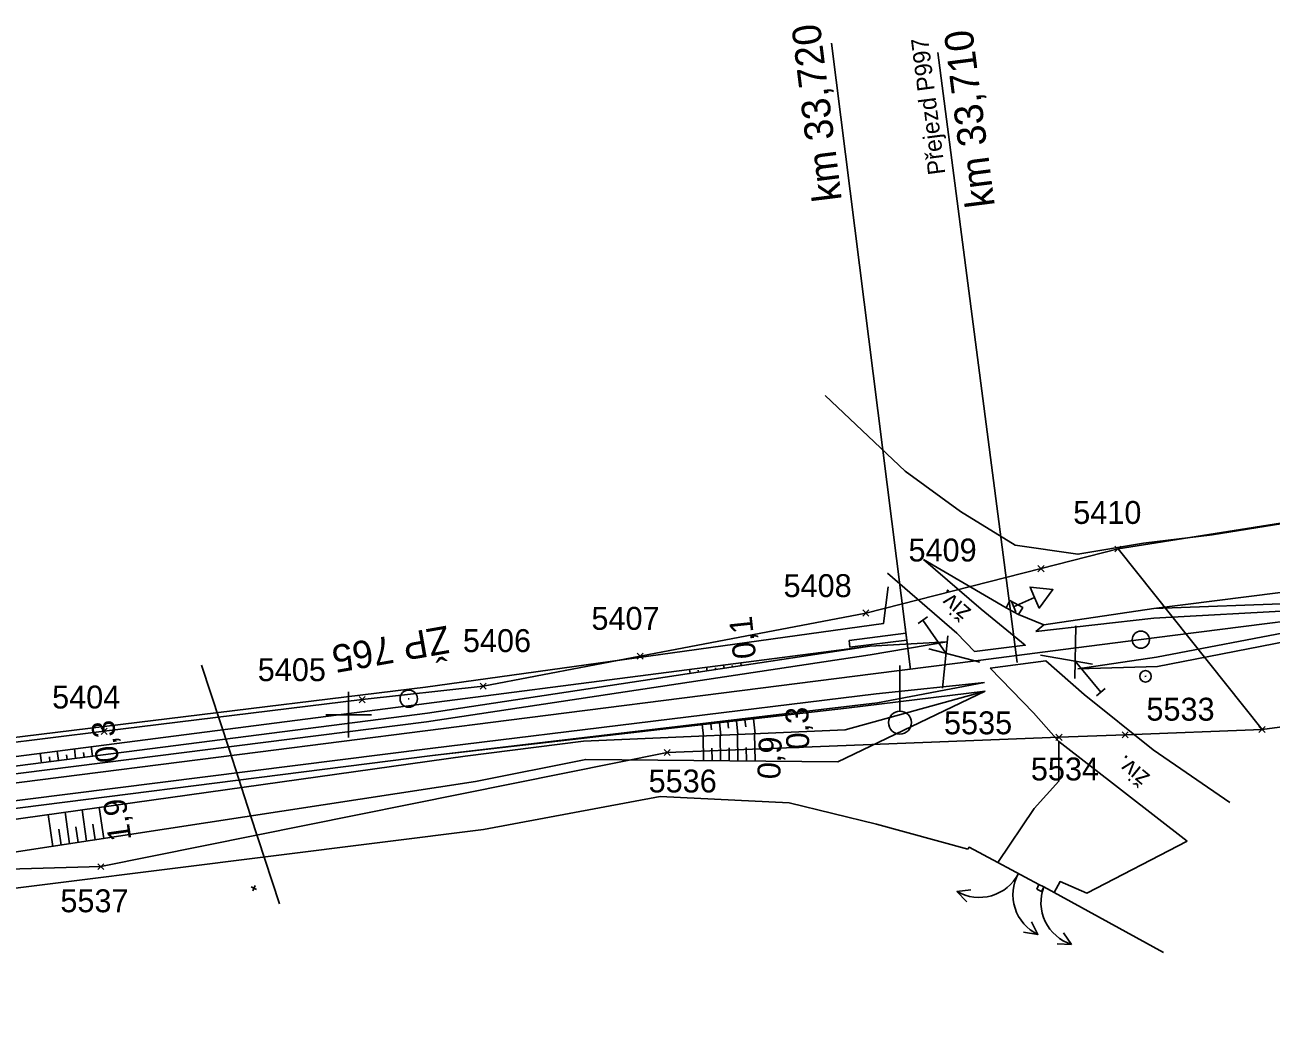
# Model space of a CAD drawing. Extents: x -805011 to -803920, y -1150790 to -1150234.
# Drawn here: x -804628.3 to -804519.5, y -1150528 to -1150439.8 of the extents above; entities that cross this region are included whole.
import ezdxf

# ---------------------------------------------------------------- set-up
doc = ezdxf.new("R2010")
doc.units = 0
for name, color, linetype in [('0381KM032-037P - Vrstva 1', 7, 'Continuous'), ('0381KM032-037P - Vrstva 12', 7, 'Continuous'), ('0381KM032-037P - Vrstva 17', 7, 'Continuous'), ('0381KM032-037P - Vrstva 25', 7, 'Continuous'), ('0381KM032-037P - Vrstva 36', 7, 'Continuous'), ('0381KM032-037P - Vrstva 4', 7, 'Continuous'), ('0381KM032-037P - Vrstva 48', 7, 'Continuous'), ('0381KM032-037P - Vrstva 49', 7, 'Continuous'), ('0381KM032-037P - Vrstva 51', 7, 'Continuous'), ('0381KM032-037P - Vrstva 55', 7, 'Continuous'), ('0381KM032-037P - Vrstva 7', 7, 'Continuous'), ('0381KM032-037P - Vrstva 9', 7, 'Continuous'), ('krizky_1000 - Vrstva 1', 7, 'Continuous'), ('szdc - hran DP', 7, 'Continuous'), ('szdc - szdc_cislo', 7, 'Continuous'), ('szdc - szdc_krizek', 7, 'Continuous'), ('vyt_sit - stávající', 7, 'Continuous')]:
    doc.layers.add(name, color=color, linetype=linetype)

msp = doc.modelspace()

# ---------------------------------------------------------------- linework, layer by layer
at = {"layer": '0381KM032-037P - Vrstva 1'}
msp.add_lwpolyline([(-804485.9, -1150487.74), (-804508.11, -1150490.55), (-804529.67, -1150493.3), (-804537.63, -1150494.31), (-804546.61, -1150495.46), (-804554.2, -1150496.42), (-804564.05, -1150497.67), (-804586.01, -1150500.48), (-804607.92, -1150503.26), (-804630.35, -1150506.11), (-804652.65, -1150508.9), (-804675.7, -1150511.78), (-804698.85, -1150514.71), (-804701.61, -1150515.06), (-804722.18, -1150517.67), (-804729.05, -1150518.54), (-804735.1, -1150519.31), (-804744.56, -1150520.5), (-804767.65, -1150523.46), (-804791, -1150526.42)], dxfattribs=at)
at = {"layer": '0381KM032-037P - Vrstva 12'}
for p, q in [((-804542.27, -1150490.03), (-804542.27, -1150490.03)), ((-804541.15, -1150490.64), (-804541.15, -1150490.64))]:
    msp.add_line(p, q, dxfattribs=at)
msp.add_lwpolyline([(-804542.6, -1150490.68), (-804542.27, -1150490.03), (-804541.15, -1150490.64), (-804541.52, -1150491.26), (-804542.6, -1150490.68), (-804542.27, -1150490.03), (-804541.15, -1150490.64), (-804541.52, -1150491.26)], dxfattribs=at)
at = {"layer": '0381KM032-037P - Vrstva 17'}
for p, q in [((-804553.92, -1150509.55), (-804545.93, -1150511.73)), ((-804539.31, -1150515.02), (-804528.85, -1150520.76)), ((-804546.89, -1150515.44), (-804546.02, -1150516.35)), ((-804539.82, -1150519.19), (-804541.07, -1150518.98)), ((-804536.89, -1150520.06), (-804537.59, -1150519.06)), ((-804538.15, -1150520.02), (-804536.89, -1150520.06)), ((-804536.89, -1150520.06), (-804538.15, -1150520.02))]:
    msp.add_line(p, q, dxfattribs=at)
for points in [[(-804368.54, -1150462.33), (-804374.42, -1150462.03), (-804388.45, -1150464.13), (-804427.08, -1150469.25), (-804429.72, -1150469.73), (-804431.75, -1150470.1), (-804437.24, -1150471.08), (-804446.96, -1150472.02), (-804473.97, -1150476), (-804503.76, -1150480.94), (-804524.61, -1150484.28), (-804530.6, -1150485.02), (-804536.33, -1150485.99), (-804541.81, -1150485.21), (-804546.58, -1150482.25), (-804551.41, -1150478.74), (-804558.4, -1150472.14)], [(-804552.89, -1150488.84), (-804553.29, -1150492.03), (-804593.3, -1150497.6), (-804640.86, -1150503.43), (-804657.42, -1150505.51), (-804657.62, -1150505.23), (-804688.14, -1150507.97), (-804701.71, -1150508.32), (-804722.68, -1150510.59), (-804720.85, -1150507.4)], [(-804731.29, -1150527.98), (-804729.95, -1150523.81), (-804721.9, -1150522.89), (-804700.75, -1150520.73), (-804652.77, -1150518.11), (-804588.21, -1150510.02), (-804572.8, -1150507.15), (-804561.55, -1150507.7), (-804553.92, -1150509.55)], [(-804545.93, -1150511.73), (-804545.83, -1150511.58), (-804543.33, -1150512.91)], [(-804539.92, -1150515.23), (-804539.73, -1150514.83), (-804539.31, -1150515.02)], [(-804539.92, -1150515.23), (-804539.5, -1150515.43), (-804539.31, -1150515.02)], [(-804546.02, -1150516.35), (-804546.89, -1150515.44), (-804545.68, -1150515.29)], [(-804541.07, -1150518.98), (-804539.82, -1150519.19), (-804540.38, -1150518.1)]]:
    msp.add_lwpolyline(points, dxfattribs=at)
for centre, start, end in [((-804544.94, -1150512.13), 239.5292, 333.049), ((-804538.17, -1150515.73), 150.9796, 244.4995), ((-804535.73, -1150516.4), 158.9316, 252.4515)]:
    msp.add_arc(centre, 3.83, start, end, dxfattribs=at)
at = {"layer": '0381KM032-037P - Vrstva 25'}
msp.add_lwpolyline([(-804612.83, -1150495.66), (-804610.41, -1150503.1), (-804608.55, -1150508.81), (-804606.04, -1150516.52)], dxfattribs=at)
at = {"layer": '0381KM032-037P - Vrstva 36'}
for p, q in [((-804551.87, -1150499.69), (-804551.87, -1150495.69)), ((-804551.87, -1150500.69), (-804551.87, -1150500.69))]:
    msp.add_line(p, q, dxfattribs=at)
msp.add_circle((-804551.87, -1150500.69), 1, dxfattribs=at)
at = {"layer": '0381KM032-037P - Vrstva 4'}
for p, q in [((-804541.64, -1150495.45), (-804548.57, -1150442.16)), ((-804515.79, -1150490.21), (-804529.7, -1150490.74)), ((-804515.61, -1150490.8), (-804529.7, -1150491.57)), ((-804549.45, -1150491.46), (-804550.27, -1150492.03)), ((-804549.86, -1150491.75), (-804547.86, -1150494.62)), ((-804529.7, -1150491.57), (-804540.01, -1150492.74)), ((-804536.6, -1150496.85), (-804536.52, -1150492.24)), ((-804515.43, -1150492.3), (-804529.48, -1150494.97)), ((-804547.69, -1150493.1), (-804548.16, -1150497.69)), ((-804515.37, -1150493.06), (-804529.38, -1150495.79)), ((-804593.11, -1150499.86), (-804554.49, -1150494.02)), ((-804547.76, -1150493.63), (-804554.49, -1150494.02)), ((-804547.76, -1150493.63), (-804554.48, -1150494.77)), ((-804544.88, -1150495.41), (-804549.34, -1150494.25)), ((-804537.63, -1150494.31), (-804546.61, -1150495.46)), ((-804593.19, -1150500.62), (-804554.48, -1150494.77)), ((-804539.6, -1150494.79), (-804535.05, -1150495.58)), ((-804534.33, -1150498.02), (-804536.56, -1150495.33)), ((-804536.34, -1150495.99), (-804529.48, -1150494.97)), ((-804529.38, -1150495.79), (-804536.34, -1150495.99)), ((-804544.49, -1150497.19), (-804553.94, -1150498.18)), ((-804553.83, -1150498.96), (-804544.49, -1150497.19)), ((-804534.71, -1150498.34), (-804533.94, -1150497.7)), ((-804553.94, -1150498.18), (-804592.89, -1150502.96)), ((-804592.67, -1150503.55), (-804553.83, -1150498.96))]:
    msp.add_line(p, q, dxfattribs=at)
for points in [[(-804540.01, -1150492.74), (-804539.3, -1150492.14), (-804529.7, -1150490.74)], [(-804593.11, -1150499.86), (-804640.49, -1150505.94), (-804687.8, -1150511.91), (-804699.22, -1150512.12)], [(-804593.19, -1150500.62), (-804640.38, -1150506.6), (-804687.82, -1150512.54), (-804699.1, -1150513.12)], [(-804592.89, -1150502.96), (-804640.05, -1150508.88), (-804687.61, -1150514.59), (-804699.07, -1150516.32)], [(-804592.67, -1150503.55), (-804639.94, -1150509.55), (-804687.3, -1150515.71), (-804688.22, -1150515.92)]]:
    msp.add_lwpolyline(points, dxfattribs=at)
at = {"layer": '0381KM032-037P - Vrstva 48'}
for p, q in [((-804565.74, -1150495.72), (-804565.77, -1150495.47)), ((-804570.19, -1150496.39), (-804570.24, -1150496.05)), ((-804569.44, -1150496.28), (-804569.47, -1150496.12)), ((-804568.7, -1150496.17), (-804568.75, -1150495.86)), ((-804567.96, -1150496.06), (-804567.98, -1150495.91)), ((-804567.22, -1150495.94), (-804567.26, -1150495.67)), ((-804566.48, -1150495.83), (-804566.5, -1150495.7)), ((-804569.12, -1150500.87), (-804569.01, -1150501.87)), ((-804568.38, -1150500.79), (-804568.32, -1150501.31)), ((-804567.63, -1150500.7), (-804567.51, -1150501.8)), ((-804566.89, -1150500.62), (-804566.82, -1150501.19)), ((-804566.14, -1150500.53), (-804566.01, -1150501.74)), ((-804565.4, -1150500.45), (-804565.33, -1150501.07)), ((-804564.65, -1150500.36), (-804564.5, -1150501.67)), ((-804569.02, -1150504), (-804569.05, -1150501.87)), ((-804567.52, -1150504.01), (-804567.55, -1150501.8)), ((-804566.02, -1150504.03), (-804566.05, -1150501.74)), ((-804564.51, -1150504.04), (-804564.55, -1150501.67)), ((-804625.33, -1150504), (-804625.43, -1150503.17)), ((-804623.84, -1150503.8), (-804623.94, -1150502.98)), ((-804622.35, -1150503.61), (-804622.46, -1150502.79)), ((-804568.27, -1150504.01), (-804568.28, -1150502.92)), ((-804566.77, -1150504.02), (-804566.78, -1150502.9)), ((-804565.26, -1150504.03), (-804565.28, -1150502.87)), ((-804626.81, -1150504.19), (-804626.92, -1150503.36)), ((-804626.07, -1150504.09), (-804626.12, -1150503.68)), ((-804624.58, -1150503.9), (-804624.63, -1150503.49)), ((-804623.09, -1150503.71), (-804623.15, -1150503.3)), ((-804624.35, -1150511.27), (-804624.75, -1150508.52)), ((-804622.87, -1150511.04), (-804623.27, -1150508.31)), ((-804621.38, -1150510.81), (-804621.78, -1150508.1)), ((-804625.83, -1150511.5), (-804626.24, -1150508.72)), ((-804622.12, -1150510.93), (-804622.33, -1150509.57)), ((-804625.09, -1150511.38), (-804625.29, -1150510)), ((-804623.61, -1150511.16), (-804623.81, -1150509.78))]:
    msp.add_line(p, q, dxfattribs=at)
at = {"layer": '0381KM032-037P - Vrstva 49'}
for p, q in [((-804554.49, -1150494.02), (-804593.11, -1150499.86)), ((-804544.42, -1150497.94), (-804556.53, -1150499.44)), ((-804608.49, -1150515.04), (-804608.04, -1150515.25)), ((-804608.15, -1150514.92), (-804608.37, -1150515.37))]:
    msp.add_line(p, q, dxfattribs=at)
for points in [[(-804541.81, -1150485.21), (-804536.33, -1150485.99), (-804530.6, -1150485.02), (-804524.61, -1150484.28), (-804503.76, -1150480.94), (-804473.97, -1150476), (-804446.96, -1150472.02), (-804437.24, -1150471.08), (-804431.75, -1150470.1), (-804429.72, -1150469.73), (-804427.08, -1150469.25), (-804388.45, -1150464.13), (-804374.42, -1150462.03), (-804368.54, -1150462.33), (-804346.87, -1150460.56), (-804338.71, -1150460.38), (-804328.85, -1150461.67), (-804323.06, -1150462.29), (-804320.34, -1150463.27)], [(-804529.7, -1150490.74), (-804539.3, -1150492.14), (-804541.52, -1150491.26), (-804542.6, -1150490.68), (-804549.8, -1150486.44)], [(-804516.1, -1150489.01), (-804529.7, -1150490.74)], [(-804554.49, -1150494.02), (-804593.21, -1150499.01), (-804640.53, -1150505.12), (-804688.31, -1150508.22), (-804703.24, -1150508.74), (-804722.68, -1150510.59)], [(-804544.42, -1150497.94), (-804556.65, -1150501.33), (-804579.48, -1150502.32), (-804589.81, -1150503.62), (-804675.11, -1150515.57), (-804678.92, -1150516.15)], [(-804544.42, -1150497.94), (-804557.28, -1150504.11), (-804579.29, -1150503.91), (-804588.92, -1150505.83), (-804639.29, -1150513.56), (-804678.92, -1150516.15)], [(-804593.11, -1150499.86), (-804640.49, -1150505.94), (-804687.8, -1150511.91), (-804699.22, -1150512.12)], [(-804556.53, -1150499.44), (-804592.67, -1150503.55), (-804639.94, -1150509.55), (-804678.92, -1150516.15)]]:
    msp.add_lwpolyline(points, dxfattribs=at)
at = {"layer": '0381KM032-037P - Vrstva 51'}
for p, q in [((-804544.77, -1150490.77), (-804549.8, -1150486.44)), ((-804546.9, -1150492.89), (-804552.96, -1150487.64)), ((-804542.14, -1150490.12), (-804541.74, -1150491.03)), ((-804545.36, -1150494.48), (-804546.9, -1150492.89)), ((-804540.22, -1150499.84), (-804543.98, -1150495.94))]:
    msp.add_line(p, q, dxfattribs=at)
for points in [[(-804541.94, -1150490.58), (-804540.11, -1150489.77), (-804539.71, -1150490.69), (-804538.51, -1150489.07), (-804540.51, -1150488.86), (-804540.11, -1150489.77)], [(-804545.36, -1150494.48), (-804540.93, -1150493.94), (-804544.77, -1150490.77)], [(-804543.98, -1150495.94), (-804539.14, -1150495.31), (-804535.78, -1150498.25)], [(-804535.78, -1150498.25), (-804529.76, -1150503.07), (-804523.07, -1150507.67)], [(-804540.22, -1150499.84), (-804538.01, -1150502.34), (-804526.8, -1150511.03)], [(-804538.01, -1150502.34), (-804538.01, -1150505.79), (-804540.15, -1150508.19), (-804543.33, -1150512.91), (-804539.73, -1150514.83)], [(-804538.41, -1150515.52), (-804537.89, -1150514.57), (-804535.54, -1150515.57), (-804526.8, -1150511.03)]]:
    msp.add_lwpolyline(points, dxfattribs=at)
at = {"layer": '0381KM032-037P - Vrstva 55'}
msp.add_line((-804532.83, -1150485.53), (-804520.26, -1150501.29), dxfattribs=at)
at = {"layer": '0381KM032-037P - Vrstva 7'}
msp.add_line((-804530.38, -1150496.64), (-804530.48, -1150496.66), dxfattribs=at)
for centre, radius in [((-804530.84, -1150493.45), 0.75), ((-804530.43, -1150496.65), 0.5)]:
    msp.add_circle(centre, radius, dxfattribs=at)
at = {"layer": '0381KM032-037P - Vrstva 9'}
for p, q in [((-804550.95, -1150496.05), (-804557.83, -1150441.36)), ((-804551.35, -1150492.89), (-804551.42, -1150492.3)), ((-804551.35, -1150492.89), (-804556.31, -1150493.51)), ((-804551.28, -1150493.49), (-804551.35, -1150492.89)), ((-804556.31, -1150493.51), (-804556.24, -1150494.1)), ((-804556.24, -1150494.1), (-804551.28, -1150493.49))]:
    msp.add_line(p, q, dxfattribs=at)
at = {"layer": 'krizky_1000 - Vrstva 1'}
for points in [[(-804600, -1150498), (-804600, -1150502)], [(-804602, -1150500), (-804598, -1150500)]]:
    msp.add_lwpolyline(points, dxfattribs=at)
at = {"layer": 'szdc - hran DP'}
for p, q in [((-804532.83, -1150485.53), (-804473.24, -1150476.04)), ((-804539.55, -1150487.24), (-804532.83, -1150485.53)), ((-804554.84, -1150491.12), (-804539.55, -1150487.24)), ((-804574.54, -1150494.89), (-804554.84, -1150491.12)), ((-804588.25, -1150497.51), (-804574.54, -1150494.89)), ((-804477.16, -1150495.64), (-804520.26, -1150501.29)), ((-804598.8, -1150498.68), (-804588.25, -1150497.51)), ((-804621.33, -1150501.45), (-804598.8, -1150498.68)), ((-804634.52, -1150503.07), (-804621.33, -1150501.45)), ((-804537.98, -1150501.97), (-804572.18, -1150503.29)), ((-804532.2, -1150501.75), (-804537.98, -1150501.97)), ((-804520.26, -1150501.29), (-804532.2, -1150501.75)), ((-804572.18, -1150503.29), (-804621.63, -1150513.27)), ((-804621.63, -1150513.27), (-804664.68, -1150514.39))]:
    msp.add_line(p, q, dxfattribs=at)
at = {"layer": 'szdc - szdc_krizek'}
for p, q in [((-804532.57, -1150485.79), (-804533.1, -1150485.27)), ((-804533.1, -1150485.79), (-804532.57, -1150485.27)), ((-804539.29, -1150487.51), (-804539.82, -1150486.98)), ((-804539.82, -1150487.51), (-804539.29, -1150486.98)), ((-804554.58, -1150491.39), (-804555.11, -1150490.85)), ((-804555.11, -1150491.39), (-804554.58, -1150490.85)), ((-804574.28, -1150495.16), (-804574.81, -1150494.62)), ((-804574.81, -1150495.16), (-804574.28, -1150494.62)), ((-804587.98, -1150497.78), (-804588.52, -1150497.25)), ((-804588.52, -1150497.78), (-804587.98, -1150497.25)), ((-804598.54, -1150498.95), (-804599.07, -1150498.42)), ((-804599.07, -1150498.95), (-804598.54, -1150498.42)), ((-804621.07, -1150501.72), (-804621.6, -1150501.19)), ((-804621.6, -1150501.72), (-804621.07, -1150501.19)), ((-804537.71, -1150502.24), (-804538.25, -1150501.71)), ((-804538.25, -1150502.24), (-804537.71, -1150501.71)), ((-804531.94, -1150502.02), (-804532.47, -1150501.49)), ((-804532.47, -1150502.02), (-804531.94, -1150501.49)), ((-804519.99, -1150501.55), (-804520.53, -1150501.03)), ((-804520.53, -1150501.55), (-804519.99, -1150501.03)), ((-804571.92, -1150503.55), (-804572.45, -1150503.03)), ((-804572.45, -1150503.55), (-804571.92, -1150503.03)), ((-804621.36, -1150513.53), (-804621.9, -1150513.01)), ((-804621.9, -1150513.53), (-804621.36, -1150513.01))]:
    msp.add_line(p, q, dxfattribs=at)
at = {"layer": 'vyt_sit - stávající'}
msp.add_line((-804594.8, -1150498.6), (-804594.7, -1150498.6), dxfattribs=at)
msp.add_circle((-804594.75, -1150498.6), 0.756, dxfattribs=at)

# ---------------------------------------------------------------- texts
at = {"layer": '0381KM032-037P - Vrstva 4'}
for s, height, p in [('Přejezd P997', 1.5, (-804547.9, -1150452.76)), ('km 33,710', 2.5, (-804543.58, -1150455.56))]:
    msp.add_text(s, height=height, rotation=97.2836, dxfattribs=at).set_placement(p)
at = {"layer": '0381KM032-037P - Vrstva 48'}
for s, rotation, p in [('0,1', 96.0264, (-804564.42, -1150495.02)), ('0,3', 91.5025, (-804559.78, -1150503.01)), ('0,3', 97.3526, (-804620.03, -1150504.07)), ('0,9', 87.4636, (-804562.33, -1150505.67)), ('1,9', 97.9771, (-804618.96, -1150510.9))]:
    msp.add_text(s, height=2, rotation=rotation, dxfattribs=at).set_placement(p)
at = {"layer": '0381KM032-037P - Vrstva 51'}
for rotation, p in [(139.2713, (-804545.56, -1150490.88)), (140.5584, (-804529.95, -1150505.32))]:
    msp.add_text('živ.', height=1.5, rotation=rotation, dxfattribs=at).set_placement(p)
at = {"layer": '0381KM032-037P - Vrstva 9'}
msp.add_text('km 33,720', height=2.5, rotation=97.0859, dxfattribs=at).set_placement((-804556.94, -1150455.05))
at = {"layer": 'szdc - szdc_cislo'}
for s, p in [('5410', (-804536.74, -1150483.34)), ('5409', (-804551.12, -1150486.62)), ('5408', (-804562.03, -1150489.73)), ('5407', (-804578.8, -1150492.59)), ('5406', (-804590.02, -1150494.53)), ('5405', (-804607.93, -1150497.07)), ('5404', (-804625.88, -1150499.46)), ('5533', (-804530.35, -1150500.52)), ('5535', (-804548.02, -1150501.71)), ('5534', (-804540.44, -1150505.74)), ('5536', (-804573.81, -1150506.79)), ('5537', (-804625.16, -1150517.25))]:
    msp.add_text(s, height=2, dxfattribs=at).set_placement(p)
at = {"layer": 'vyt_sit - stávající'}
msp.add_text('ŽP 765', height=2.4, rotation=190, dxfattribs=at).set_placement((-804591.41, -1150492.21))

doc.saveas('drawing.dxf')
